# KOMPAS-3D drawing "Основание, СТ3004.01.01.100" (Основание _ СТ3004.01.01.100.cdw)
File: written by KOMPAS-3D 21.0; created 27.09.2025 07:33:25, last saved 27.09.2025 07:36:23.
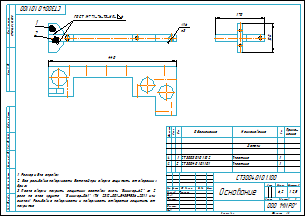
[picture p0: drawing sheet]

Sheet 1: A3, landscape

Document properties: Полное имя файла: C:\Users\Lutik\Yandex.Disk\Документы\Новая папка\Стапель №2\Стапель _ СТ3004.00.00.000\Опора _ СТ3004.01.00.000\2D\Кронштейн _ СТ3004.01.01.000\Основание _ СТ3004.01.01.100\Основание _ СТ3004.01.01.100.cdw; Масса: 6.204975

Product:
- Part/product: Основание  | designation СТ3004.01.01.100
    Масса: 6.204975
  - Component [detail]: Пластина  | designation СТ3004.01.01.101  | pos. 2  | Материал: Лист$dБ-ПН-НО-25 ГОСТ 19903-2015;Ст3сп ГОСТ 14637-89$ (density 7850 kg/m3); Масса: 5.762144; Форматы листов документа: A2; source file: ..\..\..\3D\Кронштейн _ СТ3004.01.01.000\Основание _ СТ3004.01.01.100\Пластина _ СТ3004.01.01.101.m3d, Пластина _ СТ3004.01.01.101.cdw
  - Component [detail]: Пластина  | designation СТ3003.01.01.102  | pos. 1  | Материал: Лист$dБ-ПН-НО-16 ГОСТ 19903-2015;Ст3сп ГОСТ 14637-89$ (density 7850 kg/m3); Масса: 0.442831; Форматы листов документа: A4; source file: ..\..\..\..\..\Стапель _ СТ3003.00.00.000\Опора _ СТ3003.01.00.000\3D\Кронштейн _ СТ3003.01.01.000\Основание _ СТ3003.01.01.100\Пластина _ СТ3003.01.01.102.m3d

Title block, sheet 1: Наименование: Основание; designation: СТ3004.01.01.100; Масса: 6,2; Количество листов документа: 1; organisation: ООО "МИРО"; Форматы листов документа: A3; Разработал: Тимонин

Views: Вид 1, Спереди
Referenced files in C:\Users\Lutik\Yandex.Disk\Документы\Новая папка\Стапель №2\Стапель _ СТ3004.00.00.000\Опора _ СТ3004.01.00.000\3D\Кронштейн _ СТ3004.01.01.000\Основание _ СТ3004.01.01.100\: Основание _ СТ3004.01.01.100.a3d, Пластина _ СТ3004.01.01.101.m3d
Referenced files in C:\Users\Lutik\Yandex.Disk\Документы\Новая папка\Стапель №2\Стапель _ СТ3004.00.00.000\Опора _ СТ3004.01.00.000\2D\Кронштейн _ СТ3004.01.01.000\Основание _ СТ3004.01.01.100\: Пластина _ СТ3004.01.01.101.cdw
Referenced files in C:\Users\Lutik\Yandex.Disk\Документы\Новая папка\Стапель №2\Стапель _ СТ3003.00.00.000\Опора _ СТ3003.01.00.000\3D\Кронштейн _ СТ3003.01.01.000\Основание _ СТ3003.01.01.100\: Пластина _ СТ3003.01.01.102.m3d
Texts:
  ГОСТ 14771-76-Т3-УП- 6
  СТ3004.01.01.101
  Пластина
  СТ3003.01.01.102
  СТ3004.01.01.000
  СТ3004.01.01.101 Пластина
  СТ3003.01.01.102 Пластина
  СТ3004.01.01.100 Основание
Dimensions and other numbers on the sheet: 1; 2; 16; 9; 1:2,5; 6,2

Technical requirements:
  Размеры для справок.
  Все резьбовые поверхности деталей при сварке защитить от сварочных
  брызг.
  После сварки покрыть защитным составом эмаль "Виникор-62" за 2
  раза по слою грунта  "Виникор-061" (ТУ 2312-001-54359536-2011 или
  аналог). Резьбовые поверхности и поверхность отверстия защитить от
  покрытия.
